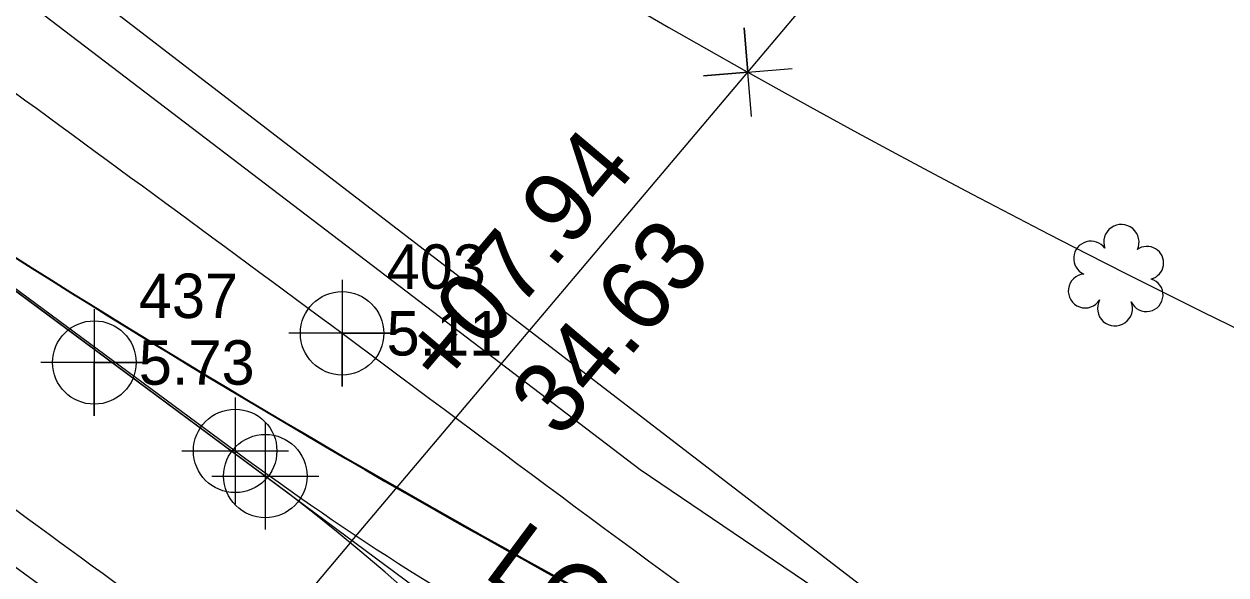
# Model space of a CAD drawing. Extents: x 2597630 to 2605918, y 617194 to 635093.
# Drawn here: x 2605028.3 to 2605095.9, y 618553.8 to 618584.8 of the extents above; entities that cross this region are included whole.
import ezdxf

# ---------------------------------------------------------------- set-up
doc = ezdxf.new("R2010")
doc.units = 0
for name, color, linetype in [('COGO Default Chain', 7, 'Continuous'), ('COGO Default Curve', 7, 'Continuous'), ('Cogo Default Point CELL', 7, 'Continuous'), ('Default Symbol Text', 7, 'Continuous'), ('Exist DTM Crownline Cogo Elevation', 7, 'Continuous'), ('Exist DTM Crownline Cogo Number', 7, 'Continuous'), ('Exist DTM Crownline Cogo Point CELL', 7, 'Continuous'), ('Exist Horizontal Alignment', 7, 'Continuous'), ('Exist Property Corner CELL', 7, 'Continuous'), ('Exist Property Line', 7, 'Continuous'), ('Exist Property Tie Line', 7, 'Continuous'), ('Exist Right of Way Line', 7, 'Continuous'), ('Exist Roads EOP', 7, 'Continuous'), ('Exist Roads EOP Cogo Elevation', 7, 'Continuous'), ('Exist Roads EOP Cogo Number', 7, 'Continuous'), ('Exist Roads EOP Cogo Point CELL', 7, 'Continuous'), ('Exist Utilities Telephone UG Cable SUE LOS C', 7, 'Continuous'), ('Exist Vegetation Shrub CELL', 7, 'Continuous'), ('Raster_Level_3', 7, 'Continuous')]:
    doc.layers.add(name, color=color, linetype=linetype)

# ---------------------------------------------------------------- blocks, each defined once
blk = doc.blocks.new('EXIST VEGETATION SHRUB')
at = {"layer": 'Exist Vegetation Shrub CELL'}
blk.add_line((0, 0), (0, 0), dxfattribs=at)
for centre, radius, start, end in [((0.0046, 0.0408), 0.0198, 334.8391, 200.4717), ((-0.0297, 0.0225), 0.0194, 35.8908, 245.4216), ((0.0334, 0.0174), 0.0186, 284.4567, 126.0861), ((-0.036, -0.0141), 0.0191, 95.1099, 327.9534), ((0.0327, -0.0186), 0.0187, 204.9913, 73.4601), ((-0.0026, -0.0337), 0.0197, 151.2797, 21.387)]:
    blk.add_arc(centre, radius, start, end, dxfattribs=at)
blk = doc.blocks.new('EXIST DTM CROWNLINE COGO POINT')
at = {"layer": 'Exist DTM Crownline Cogo Point CELL'}
blk.add_lwpolyline([(0, 0.06), (0, -0.06), (0, 0), (0.06, 0), (-0.06, 0)], dxfattribs=at)
blk.add_circle((0, 0), 0.0469, dxfattribs=at)
blk = doc.blocks.new('EXIST ROADS EOP COGO POINT')
at = {"layer": 'Exist Roads EOP Cogo Point CELL'}
blk.add_lwpolyline([(0, 0.06), (0, -0.06), (0, 0), (0.06, 0), (-0.06, 0)], dxfattribs=at)
blk.add_circle((0, 0), 0.0469, dxfattribs=at)

msp = doc.modelspace()

# ---------------------------------------------------------------- linework, layer by layer
at = {"layer": 'COGO Default Chain'}
for p, q in [((2604635.42, 618891.582), (2605209.537, 618450.053)), ((2604635.42, 618891.582), (2605209.537, 618450.053)), ((2604906.9, 618659.448), (2605040.188, 618560.796)), ((2604906.9, 618659.448), (2605092.435, 618521.9)), ((2604906.9, 618659.448), (2605092.435, 618521.9)), ((2604906.9, 618659.448), (2605040.188, 618560.796)), ((2605041.881, 618559.379), (2604906.9, 618659.448)), ((2604906.9, 618659.448), (2605092.435, 618521.9)), ((2604906.9, 618659.448), (2605040.188, 618560.796))]:
    msp.add_line(p, q, dxfattribs=at)
for centre, radius, start, end in [((2605334.316, 619054.493), 571.893, 233.44825, 249.95735), ((2605334.316, 619054.493), 571.893, 233.44825, 249.95735), ((2605334.316, 619054.493), 571.893, 233.44825, 249.95735), ((2605138.207, 618693.141), 164.69, 233.47492, 250.01646), ((2605138.207, 618693.141), 164.69, 233.47492, 250.01646), ((2605138.207, 618693.141), 164.69, 233.47492, 250.01646), ((2604976.371, 618471.014), 110, 356.74026, 53.44825)]:
    msp.add_arc(centre, radius, start, end, dxfattribs=at)
at = {"layer": 'COGO Default Curve'}
for centre, radius, start, end in [((2605334.316, 619054.493), 571.893, 233.44825, 249.95735), ((2605334.316, 619054.493), 571.893, 233.44825, 249.95735), ((2605138.207, 618693.141), 164.69, 233.47492, 250.01646), ((2605138.207, 618693.141), 164.69, 233.47492, 250.01646), ((2604976.371, 618471.014), 110, 356.74026, 53.44825)]:
    msp.add_arc(centre, radius, start, end, dxfattribs=at)
at = {"layer": 'Cogo Default Point CELL'}
for points in [[(2605040.188, 618563.796), (2605040.188, 618560.796)], [(2605041.881, 618562.379), (2605041.881, 618559.379)], [(2605037.188, 618560.796), (2605040.188, 618560.796)], [(2605040.188, 618560.796), (2605043.188, 618560.796)], [(2605040.188, 618560.796), (2605040.188, 618557.796)], [(2605038.881, 618559.379), (2605041.881, 618559.379)], [(2605041.881, 618559.379), (2605044.881, 618559.379)], [(2605041.881, 618559.379), (2605041.881, 618556.379)]]:
    msp.add_lwpolyline(points, dxfattribs=at)
for centre in [(2605040.188, 618560.796), (2605041.881, 618559.379)]:
    msp.add_circle(centre, 2.344, dxfattribs=at)
at = {"layer": 'Exist Horizontal Alignment'}
msp.add_line((2604906.9, 618659.448), (2605092.435, 618521.9), dxfattribs=at)
msp.add_arc((2605334.316, 619054.493), 571.893, 233.44825, 249.95735, dxfattribs=at)
at = {"layer": 'Exist Property Corner CELL'}
msp.add_line((2605068.991, 618582.096), (2605068.991, 618582.096), dxfattribs=at)
msp.add_lwpolyline([(2605069.202, 618579.604), (2605068.78, 618584.587), (2605068.991, 618582.096), (2605066.5, 618581.885), (2605071.482, 618582.306)], dxfattribs=at)
at = {"layer": 'Exist Property Line'}
msp.add_line((2605068.991, 618582.096), (2605120.379, 618642.984), dxfattribs=at)
at = {"layer": 'Exist Property Tie Line'}
for q in [(2605068.991, 618582.096), (2605027.463, 618532.891)]:
    msp.add_line((2605046.655, 618555.631), q, dxfattribs=at)
at = {"layer": 'Exist Right of Way Line'}
msp.add_arc((2605334.316, 619054.493), 541.808, 233.44825, 249.91603, dxfattribs=at)
at = {"layer": 'Exist Roads EOP'}
for points in [[(2604973.794, 618621.175), (2605003.899, 618598.528), (2605046.196, 618567.408), (2605072.515, 618548.047), (2605103.618, 618527.364), (2605140.117, 618505.161), (2605178.033, 618485.562), (2605220.739, 618472.458), (2605259.093, 618465.195), (2605301.774, 618462.969), (2605350.348, 618466.747), (2605390.569, 618472.395), (2605430.003, 618479.657), (2605472.601, 618488.42), (2605517.963, 618498.678), (2605555.274, 618508.222)], [(2605554.931, 618488.691), (2605518.323, 618479.552), (2605476.771, 618470.314), (2605429.068, 618460.66), (2605388.393, 618453.139), (2605342.247, 618446.788), (2605297.978, 618443.933), (2605250.493, 618446.948), (2605224.746, 618451.291), (2605188.067, 618461.914), (2605143.175, 618481.98), (2605101.821, 618506.05), (2605057.725, 618535.842), (2605018.828, 618564.087), (2604984.62, 618589.304), (2604956.97, 618610.183)]]:
    msp.add_spline(points, degree=3, dxfattribs=at)
at = {"layer": 'Exist Utilities Telephone UG Cable SUE LOS C'}
for points in [[(2604704.632, 618797.902), (2604709.253, 618799.967), (2604746.093, 618830.902), (2604769.465, 618803.801), (2604789.101, 618780.394), (2604811.521, 618758.153), (2604839.523, 618732.525), (2604857.937, 618716.819), (2604890.546, 618690.254), (2604917.08, 618668.966), (2604949.989, 618644.104), (2604978.651, 618623.009), (2605029.128, 618585.555), (2605062.936, 618559.757), (2605107.482, 618529.542), (2605127.562, 618516.387), (2605160.551, 618498.208), (2605196.169, 618483.139), (2605231.309, 618473.571), (2605271.708, 618467.352), (2605299.025, 618467.352), (2605327.232, 618467.352), (2605372.412, 618473.385), (2605472.154, 618492.39)], [(2604704.632, 618797.902), (2604712.066, 618799.71), (2604727.398, 618812.35), (2604744.299, 618792.301), (2604764.162, 618770.77), (2604783.48, 618750.533), (2604806.287, 618728.566), (2604832.993, 618704.332), (2604851.81, 618688.555), (2604875.483, 618669.846), (2604895.582, 618654.218), (2604912.85, 618640.26), (2604940.378, 618619.514), (2604966.274, 618599.42), (2604984.743, 618585.385), (2605006.607, 618569.828), (2605030.268, 618552.498), (2605043.196, 618543.102), (2605035.066, 618529.174)]]:
    msp.add_lwpolyline(points, dxfattribs=at)
at = {"layer": 'Raster_Level_3'}
msp.add_arc((2605333.954, 619054.76), 571.893, 233.49328, 249.99328, dxfattribs=at)

# ---------------------------------------------------------------- block references
at = {"layer": 'Exist DTM Crownline Cogo Point CELL', "xscale": 50, "yscale": 50}
msp.add_blockref('EXIST DTM CROWNLINE COGO POINT', (2605032.274, 618565.767), dxfattribs=at)
msp.add_blockref('EXIST DTM CROWNLINE COGO POINT', (2605032.274, 618565.767), dxfattribs=at)
at = {"layer": 'Exist Roads EOP Cogo Point CELL', "xscale": 50, "yscale": 50}
msp.add_blockref('EXIST ROADS EOP COGO POINT', (2605046.196, 618567.408), dxfattribs=at)
msp.add_blockref('EXIST ROADS EOP COGO POINT', (2605046.196, 618567.408), dxfattribs=at)
at = {"layer": 'Exist Vegetation Shrub CELL', "xscale": 50, "yscale": 50}
msp.add_blockref('EXIST VEGETATION SHRUB', (2605089.756, 618570.496), dxfattribs=at)

# ---------------------------------------------------------------- texts
at = {"layer": 'Default Symbol Text'}
msp.add_text("LOW WIRE=28.61'", height=4, rotation=323.44825, dxfattribs=at).set_placement((2605054.036, 618553.802))
at = {"layer": 'Exist DTM Crownline Cogo Elevation'}
msp.add_text('5.73', height=2.5, dxfattribs=at).set_placement((2605034.774, 618564.517))
at = {"layer": 'Exist DTM Crownline Cogo Number'}
msp.add_text('437', height=2.5, dxfattribs=at).set_placement((2605034.774, 618568.267))
msp.add_text('437', height=2.5, dxfattribs=at).set_placement((2605034.774, 618568.267))
at = {"layer": 'Exist Property Tie Line'}
for s, p in [('+07.94', (2605052.16, 618564.042)), ('34.63', (2605058.427, 618561.39))]:
    msp.add_text(s, height=4, rotation=49.83608, dxfattribs=at).set_placement(p)
at = {"layer": 'Exist Roads EOP Cogo Elevation'}
msp.add_text('5.11', height=2.5, dxfattribs=at).set_placement((2605048.696, 618566.158))
at = {"layer": 'Exist Roads EOP Cogo Number'}
msp.add_text('403', height=2.5, dxfattribs=at).set_placement((2605048.696, 618569.908))

doc.saveas('drawing.dxf')
